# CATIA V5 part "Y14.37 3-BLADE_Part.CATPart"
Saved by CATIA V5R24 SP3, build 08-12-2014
Part number: ASME Y14.37 3-Blade Example
Bounding box of the stored display mesh (mm): x -167.089 to 167.089, y 0 to 90.545, z -167.089 to 167.089
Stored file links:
  \\Nw\787lib\787-PROCINT-WKG\Dom_SSDBS\DM\!!ShareFileForWritingServices\Composites\Standards and References\ASME Y14.37\Y14.37 3-BLADE_Part.CATPart
  C:\Program Files\Dassault Systemes\B28SP3PRALL\win_b64\startup\composites\CompositesCatalog.CATMaterial
  E:\ASME Y14.37\ASME Y-14.37_COMPOSITES.CATMaterial
  C:\Program Files\Dassault Systemes\B28SP3PRALL\win_b64\startup\composites\LaminateColors.txt
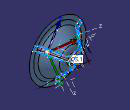
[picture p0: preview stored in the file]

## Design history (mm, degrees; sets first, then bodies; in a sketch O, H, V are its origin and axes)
CompParametersFeature1 "CATCoParametersFeatName": Value 0, Value 45, Value -45, Value 90
CompStacking1 "Stacking"
AxisSystem1 "Local Axis System": origin (0, 0, 0), X (-0.866, 0, 0.5), Y (0.5, 0, 0.866), Z (0, 1, 0)
CompReviewTools1 "Review tools"
CompEOPGroupFeature1 "CATCoEOPGroupFeatName"
Set1 "Construction Geometry (REF)"
  Sketch1 on xy-plane, origin (0, 0, 0), H (1, 0, 0), V (0, 1, 0)
    point P1 (-167.1288, 0)
    line L1 (-167.1288, 0) -> (-142.3543, 0)
    line L2 (-123.3692, 8.8246) -> (-66.4127, 76.365)
    arc A1 centre (-42.4512, 56.1584) radius 31.3442 from (-66.4127, 76.365) to (-29.9974, 84.9223) cw
    arc A2 centre (-21.0644, 105.5542) radius 22.4828 from (-29.9974, 84.9223) to (-21.0644, 83.0715) ccw
    line L3 (-21.0644, 83.0715) -> (0, 83.0715)
    point P7 (0, 83.0715)
    axis line L4 (0, 104.2142) -> (0, -35.51)
    point P8 (0, 104.2142)
    arc A3 centre (-142.3543, 24.8346) radius 24.8346 from (-142.3543, 0) to (-123.3692, 8.8246) ccw
    radius A3 = 24.8346
    coincidence: P1 H, P7 V, P8 V
    horizontal: L1 H, L3 H
    tangency: A1 L2, A2 A1, A2 L3, A3 L1, A3 L2
    vertical: L4 V
  Set2 "Engineering Geometry"
    Revol1: Element1 Sketch1, Angle1 360
  Plane1: type Offset, RefPlane yz-plane, Offset 12.7
  Plane2: type Offset, RefPlane yz-plane, Offset 12.7, reversed
  Plane3: type Angle, RefPlane yz-plane, Direction Y axis, Angle 60
  Plane4: type Angle, RefPlane Plane3, Direction Y axis, Angle 60
  MultiSel1
  Plane5: type Offset, RefPlane Plane4, Offset 12.7
  Intersect1: ToIntersect1 {inverselocal InverseElem Plane5}, ToIntersect2 Revol1
  Intersect2: ToIntersect1 {inverselocal InverseElem Plane6}, ToIntersect2 Revol1
  Plane6: type Offset, RefPlane Plane4, Offset 12.7, reversed
  Plane7: type Offset, RefPlane Plane3, Offset 12.7, reversed
  Intersect3: ToIntersect1 {inverselocal InverseElem Plane7}, ToIntersect2 Revol1
  Intersect4: ToIntersect1 {inverselocal InverseElem Plane8}, ToIntersect2 Revol1
  Plane8: type Offset, RefPlane Plane3, Offset 12.7
  Corner1: Element1 Intersect4, Element2 {intersect ToIntersect1 Plane1, ToIntersect2 Revol1}, Support Revol1, Radius 25.4
  Corner2: Element1 Intersect3, Element2 Intersect2, Support Revol1, Radius 25.4
  Corner3: Element1 {intersect ToIntersect1 Plane2, ToIntersect2 Revol1}, Element2 Intersect1, Support Revol1, Radius 25.4
  Trim1: Trimmed (Intersect2; Corner2; Intersect3)
  Trim2: Trimmed (Intersect4; Corner1; {intersect ToIntersect1 Plane1, ToIntersect2 Revol1})
  Trim3: Trimmed ({intersect ToIntersect1 Plane2, ToIntersect2 Revol1}; Corner3; Intersect1)
  Line1: type PtPt, FirstPoint vertex of Intersect1, SecondPoint vertex of Intersect2, Support Revol1
  Line2: type PtPt, FirstPoint vertex of Intersect3, SecondPoint vertex of Intersect4, Support Revol1
  Line3: type PtPt, FirstPoint vertex of MultiSel1, SecondPoint vertex of MultiSel1, Support Revol1
  CurvePar1: Offset Line1, Support Revol1, Offset2 0, Offset1 5.08
  CurvePar2: Offset Line3, Support Revol1, Offset2 0, Offset1 5.08
  CurvePar3: Offset Line2, Support Revol1, Offset2 0, Offset1 5.08
  Contour1: BaseSurface Revol1, Wires (Trim1; CurvePar1; Trim3; CurvePar2; Trim2; CurvePar3), ExtrapolLength 0.003
  Line4: type PtDir, RefPoint vertex [YZ plane of AxisSystem1 | ZX plane of AxisSystem1 | XY plane of AxisSystem1], Direction zx-plane, Start -55, End 165
  Plane9: type Angle, RefPlane yz-plane, Direction Y axis, Angle 30
  Plane10: type Angle, RefPlane yz-plane, Direction Y axis, Angle -30
  Plane11: type Offset, RefPlane zx-plane, Offset 31
  Set3 "Construction - Rosettes"
    Split1: ToCut Intersect5, Cutting (Intersect1; Intersect2)
    Near1: MultiElement Split1, ReferenceElement Line1
    Split2: ToCut Intersect5, Cutting (Intersect3; Intersect4)
    Near2: MultiElement Split2, ReferenceElement Line2
    Split3: ToCut Intersect5, Cutting ({intersect ToIntersect1 Plane1, ToIntersect2 Revol1}; {intersect ToIntersect1 Plane2, ToIntersect2 Revol1})
    Near3: MultiElement Split3, ReferenceElement Line3
    Point1: type OnCurve, Support Near1, Ratio 0.5
    Point2: type OnCurve, Support Near3, Ratio 0.5
    Point3: type OnCurve, Support Near2, Ratio 0.5
    Line5: type Normal, RefPoint Point2, RefSkin Join1, Start 0, End 25.4
    Line6: type Normal, RefPoint Point3, RefSkin Join1, Start 0, End 25.4
    Line7: type Normal, RefPoint Point1, RefSkin Join1, Start 0, End 25.4
  Point4: (1.8096, 83.0715, -11.204)
  Extract1: ExtractElem edge [face of Revol1 from Sketch1.A2 | face of Revol1 from Sketch1.A1]
Set4 "Engineering Geometry"
  Join1 "Definition Surface": Elements Revol1
  AxisSystem2 "Rosette - A": origin (-90.6458, 31, 52.3344), X (0.5583, 0.7645, -0.3223), Y (-0.5, 0, -0.866), Z (-0.662, 0.6447, 0.3822)
  AxisSystem3 "Rosette - B": origin (0, 31, -104.6688), X (0, 0.7645, 0.6447), Y (1, 0, 0), Z (0, 0.6447, -0.7645)
  AxisSystem4 "Rosette - C": origin (90.6458, 31, 52.3344), X (-0.5583, 0.7645, -0.3223), Y (-0.5, 0, 0.866), Z (0.662, 0.6447, 0.3822)
  Intersect5 "90deg Curve": ToIntersect1 Plane11, ToIntersect2 Join1
Body1 "-1 BOND ASSEMBLY" (main body)
  Solid1: solid without history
